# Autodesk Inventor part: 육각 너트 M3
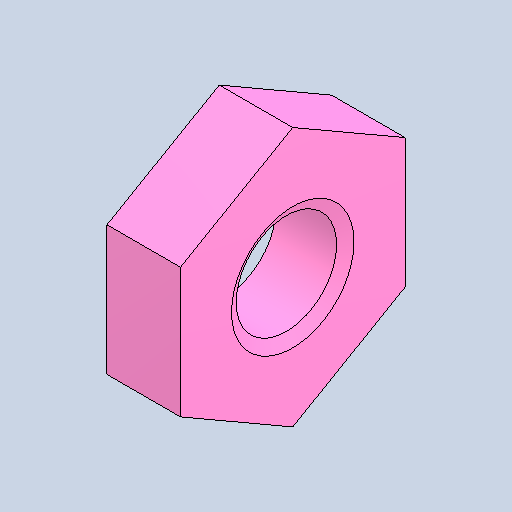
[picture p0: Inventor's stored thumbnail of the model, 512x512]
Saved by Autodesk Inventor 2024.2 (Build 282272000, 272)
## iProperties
Created: 2025-09
Part Number: 육각 너트 M3
Material: 강철, 연강
Description: 6각 너트 및 6각 가는 너트 - 모따기 안된
Document SubType Name: Modeling
Designer: home
Density: 7.85 g/cm^3
Appearance: 기본값
Author: jhkim
Sending System: Autodesk Inventor 2026
Preprocessor: ST-DEVELOPER v20.1
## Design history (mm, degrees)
feature "Solid1"
node "솔리드1"
